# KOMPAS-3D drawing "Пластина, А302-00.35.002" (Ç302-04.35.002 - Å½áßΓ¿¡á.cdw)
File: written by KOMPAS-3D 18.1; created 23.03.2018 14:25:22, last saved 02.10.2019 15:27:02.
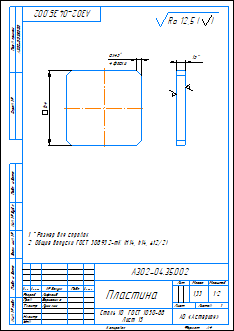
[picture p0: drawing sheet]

Sheet 1: A4, portrait

Document properties: Автор: Милов; Полное имя файла: D:\Мембранные насосы\Мембранный электропривод\А302-00.00.000 - ASTRA-302 (МЭ200)\А302-04.00.000 - Мембранный насос ASTRA-302-PP Чертежи\А302-04.35.002 - Пластина.cdw; Масса: 1.32755; Параметр неуказанной шероховатости: Ra 12,5

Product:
- Part/product: Пластина  | designation А302-00.35.002
    Масса: 0.697075
    Раздел спецификации: Детали
    Форматы листов документа: A4
  - Component: Пластина  | designation А302-00.35.002  | pos. 2  | Масса: 0.7; Раздел спецификации: Детали; Форматы листов документа: A4
- Part/product: Пластина  | designation А302-04.35.002
    Масса: 1.32755
    Раздел спецификации: Детали
    Форматы листов документа: A4
- Part/product: Пластина  | designation А302-05.35.002
    Масса: 0.658749
    Раздел спецификации: Детали
    Форматы листов документа: A4
- Part/product: Пластина  | designation А302-00.35.002-01
    Масса: 1.44135
    Раздел спецификации: Детали
    Форматы листов документа: A4

Title block, sheet 1: Наименование: Пластина; designation: А302-04.35.002; Материал: Сталь 10  ГОСТ 1050-88 / Лист 15; Масса: 1,33; scale: 1:2; Количество листов документа: 1; organisation: АО «Астерион»; Форматы листов документа: A4; stored path: \\192.168.87.28\Konstructor_doc\Мембранные насосы\Мембранный электропривод\А302-00.00.000 - ASTRA-302 (МЭ200)\Чертежи\А302-00.35.002 - Пластина.cdw; Разработал: Лифлянд; Проверил: Борисенко; Т. контр.: Лучихин

Views: Вид 1, Проекционный вид 2
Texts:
  Ra 12,5
  Ra 12,5 ( )
Dimensions and other numbers on the sheet: 134; 8; 4 фаски; 15; 1:2; 1; 1,33

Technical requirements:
  *Размер для справок.
  Общие допуски ГОСТ 30893.2-mK (H14, h14,  t2/2).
